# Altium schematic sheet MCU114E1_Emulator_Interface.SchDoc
size 431 x 279 mm; Date: Not shown in title block; ApprovedBy: Not shown in title block; CheckedBy: Not shown in title block; Author: Not shown in title block; CompanyName: Not shown in title block; Engineer: Not shown in title block; Organization: Not shown in title block; Address1: Not shown in title block; Address2: Not shown in title block; Address3: Not shown in title block; Address4: Not shown in title block; DocumentNumber: 10; Revision: Use project parameter SCH_Rev; SheetNumber: 10; SheetTotal: 11; PageSetup: Record=PageOptions¦CenterHorizontal=True¦CenterVertical=True¦PrintScale=1.00¦XCorrection=1.00¦YCorrection=1.00¦PrintKind=0¦BorderSize=5000000¦LeftOffset=0¦BottomOffset=0¦Orientation=2¦PaperLength=1000¦PaperWidth=1000¦Scale=100¦PaperSource=15¦PrintQuality=600¦MediaType=1¦DitherType=10¦PaperKind=Letter¦PrintScaleMode=1
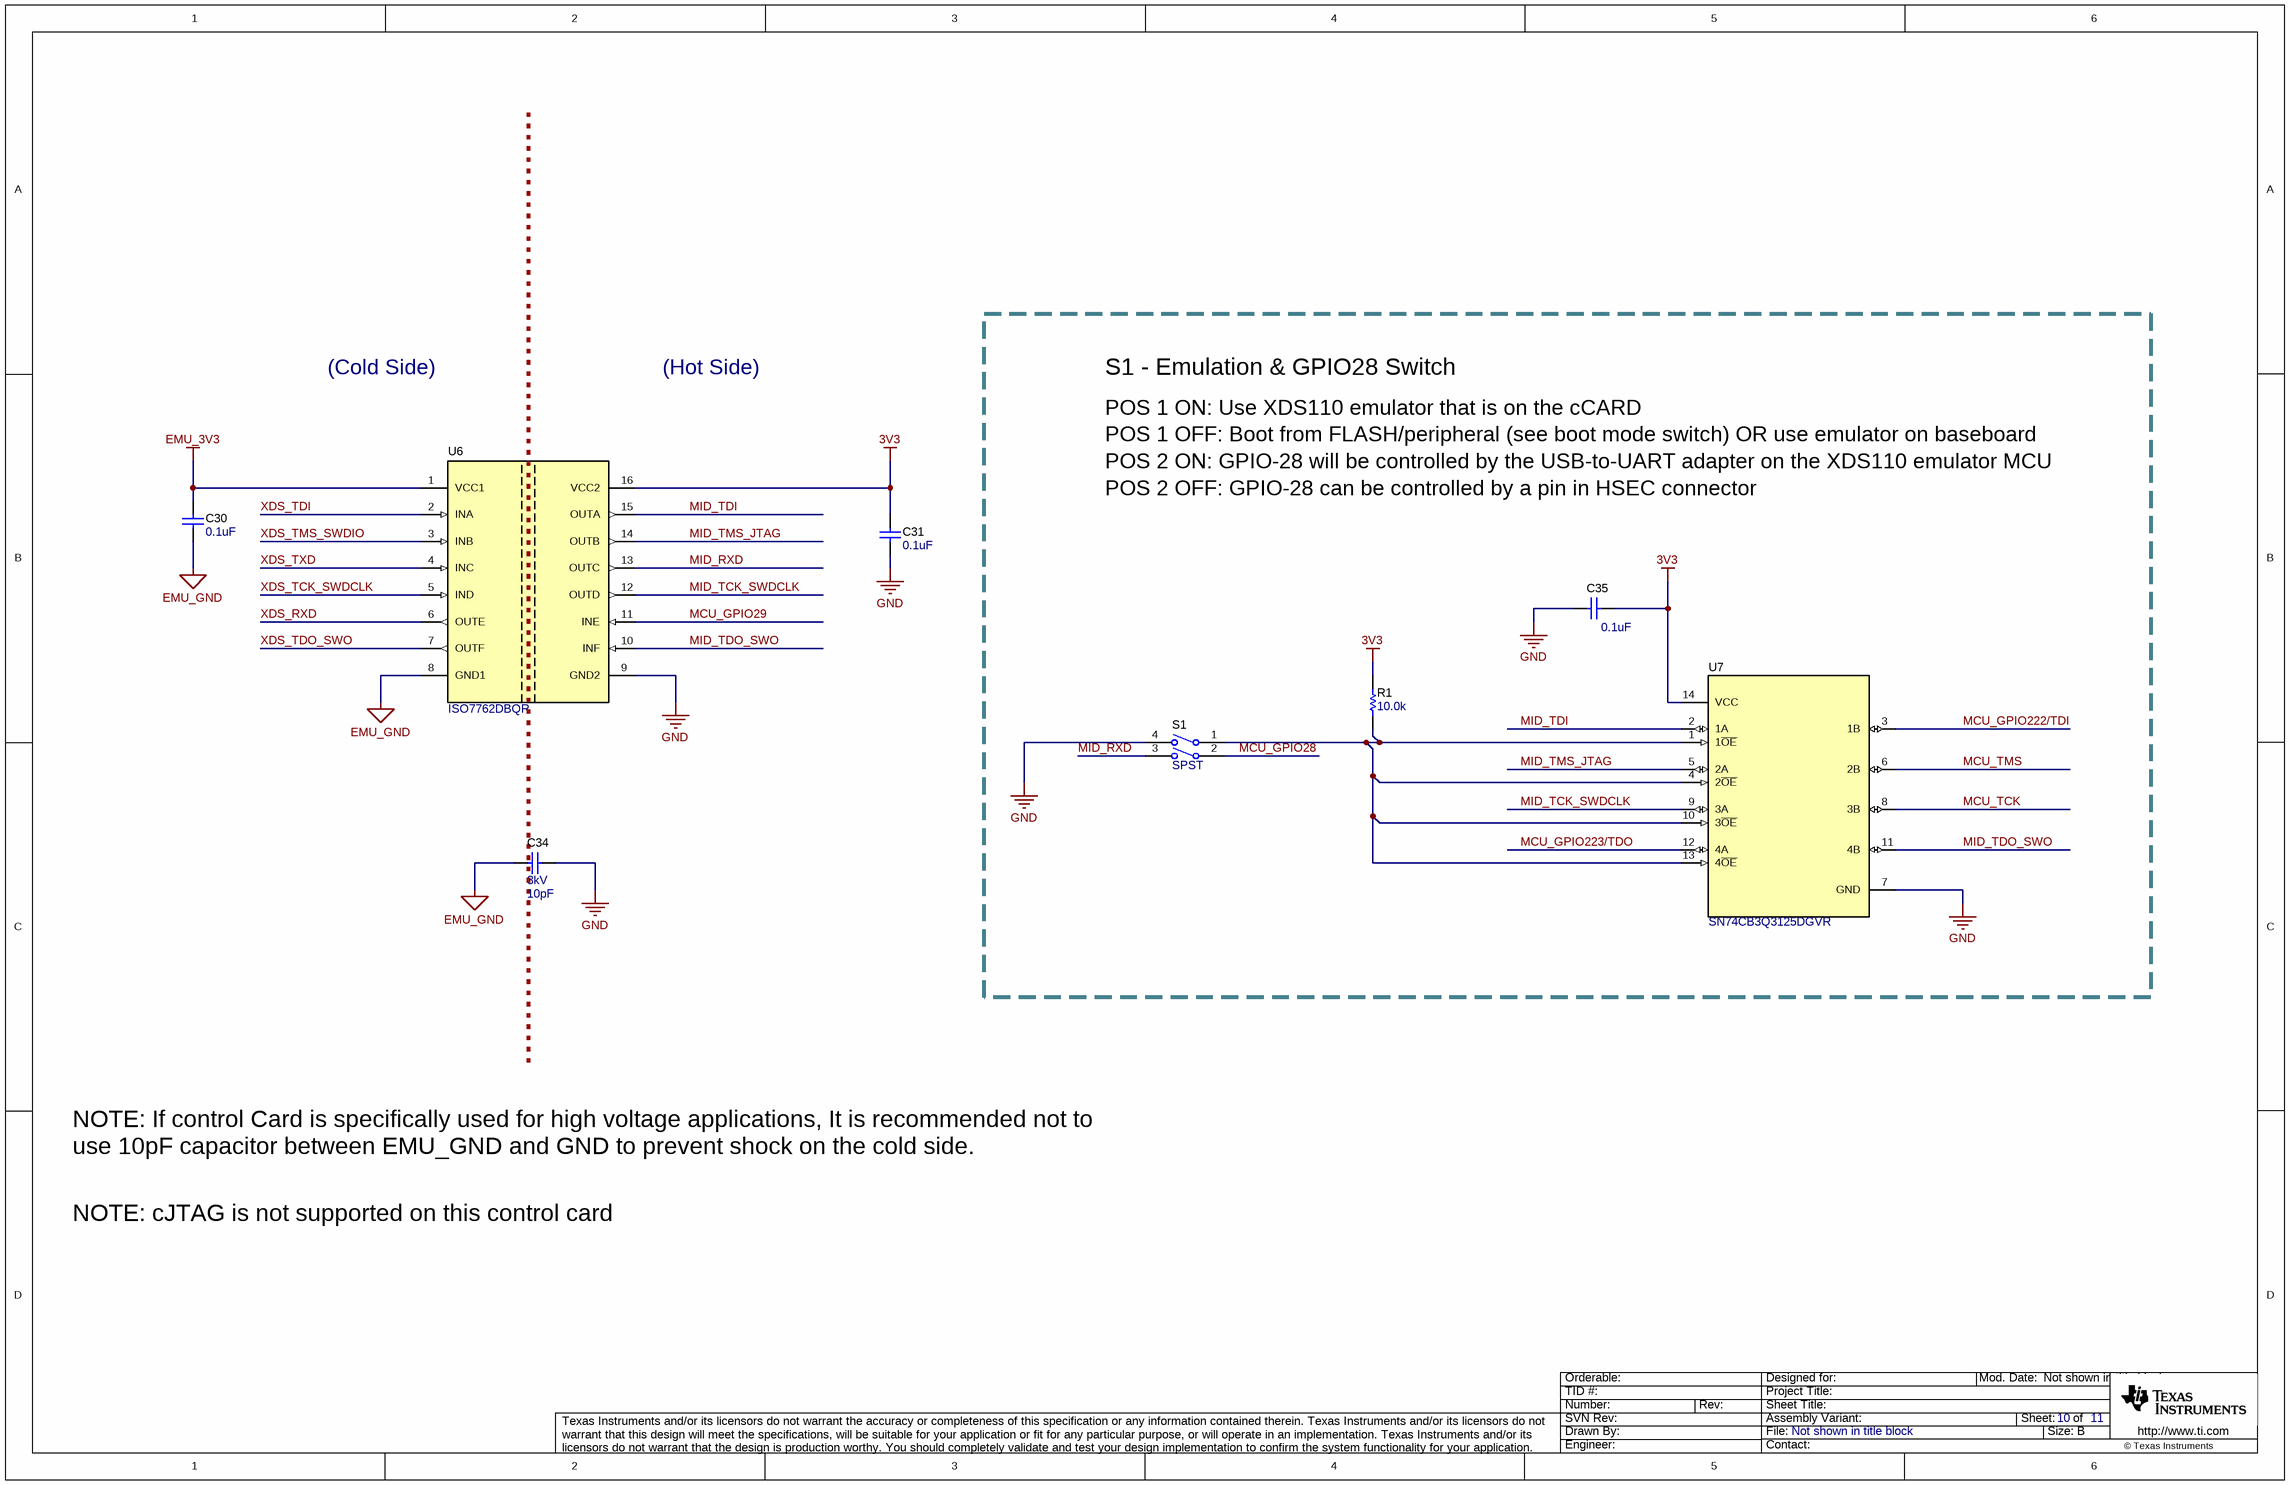
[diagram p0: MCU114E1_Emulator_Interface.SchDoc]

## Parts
C30  ValueDisplayed: 0.1uF  [0402]  (hidden comment: 885012205037)
C31  ValueDisplayed: 0.1uF  [0402]  (hidden comment: 885012205037)
C34  VDC_V: 3kV  ValueDisplayed: 10pF  [1812_180]  (hidden comment: C1812C100JHGACTU)
C35  ValueDisplayed: 0.1uF  [0402]  (hidden comment: 885012205037)
R1  ValueDisplayed: 10.0k  [0402]  (hidden comment: AC0402FR-0710KL)
S1  Circuit: SPST  [SW_218-2LP]  (hidden comment: 218-2LPST)
U6  ISO7762DBQR  [DBQ0016A_N]
U7  SN74CB3Q3125DGVR  [DGV0014A_N]

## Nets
3V3: C31.1 C35.1 R1.2 U6.16(VCC2) U7.14(VCC)
EMU_3V3: C30.1 U6.1(VCC1)
EMU_GND: C30.2 C34.2 U6.8(GND1)
GND: C31.2 C34.1 C35.2 S1.4 U6.9(GND2) U7.7(GND)
MCU_GPIO28: S1.2
MCU_GPIO29: U6.11(INE)
MCU_GPIO222/TDI: U7.3(1B)
MCU_GPIO223/TDO: U7.12(4A)
MCU_TCK: U7.8(3B)
MCU_TMS: U7.6(2B)
MID_RXD: S1.3 U6.13(OUTC)
MID_TCK_SWDCLK: U6.12(OUTD) U7.9(3A)
MID_TDI: U6.15(OUTA) U7.2(1A)
MID_TDO_SWO: U6.10(INF) U7.11(4B)
MID_TMS_JTAG: U6.14(OUTB) U7.5(2A)
XDS_RXD: U6.6(OUTE)
XDS_TCK_SWDCLK: U6.5(IND)
XDS_TDI: U6.2(INA)
XDS_TDO_SWO: U6.7(OUTF)
XDS_TMS_SWDIO: U6.3(INB)
XDS_TXD: U6.4(INC)
NetR1_1: R1.1 S1.1 U7.1(1~{OE}) U7.4(2~{OE}) U7.10(3~{OE}) U7.13(4~{OE})

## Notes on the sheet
- S1 - Emulation & GPIO28 Switch
- (Cold Side)
- (Hot Side)
- POS 1 ON: Use XDS110 emulator that is on the cCARD
- POS 1 OFF: Boot from FLASH/peripheral (see boot mode switch) OR use emulator on baseboard
- POS 2 ON: GPIO-28 will be controlled by the USB-to-UART adapter on the XDS110 emulator MCU
- POS 2 OFF: GPIO-28 can be controlled by a pin in HSEC connector
- NOTE: If control Card is specifically used for high voltage applications, It is recommended not to use 10pF capacitor between EMU_GND and GND to prevent shock on the cold side.
- NOTE: cJTAG is not supported on this control card

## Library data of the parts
C30 C31 C35 = CMP-0006228-2: CAP, CERM, 0.1 uF, 16 V, +/- 10%, X7R, 0402; Manufacturer: Wurth Elektronik; TaMin_C: -55°C; Polarized: N; SizeAreaWB_mm2: 3; Value1: Unknown; U/M: EA; Value: 0.1uF; TaMax_C: 125°C; SizeZ_mm: 0.6; SizeX_mm: 1; SizeY_mm: 0.5; Value2: 16V; Cap_F: 100nF; AEC Category: Q200
C34 = CMP-0082066-1: CAP, CERM, 10 pF, 3000 V,+/- 5%, C0G/NP0, AEC-Q200 Grade 1, 1812; Manufacturer: Kemet; SizeAreaWB_mm2: 23.1; SizeArea_mm2: 14.4; AEC Qualified: Y; AEC Category: Q200; Value: 10pF; TaMax_C: 125°C; SizeZ_mm: 1.8; AEC Grade: 1; Polarized: N; TaMin_C: -55°C; SizeY_mm: 3.2; Value2: 3000V; U/M: EA; SizeX_mm: 4.5; Cap_Case: 1812
R1 = CMP-0077731-1: RES, 10.0 k, 1%, 0.063 W, AEC-Q200 Grade 0, 0402; Manufacturer: Yageo America; Power_W: 63mW; TempCo: 100 ppm/C; Value_Code: 10k0; U/M: EA; Value: 10.0k; EIA_Code: E96; Res_ohm: 10k; SizeX_mm: 1.0; SizeY_mm: 0.5; SizeZ_mm: 0.6; Value2: 0.063W; AEC Qualified: Y; VDC_V: 50V; AEC Grade: 0; AEC Category: Q200
S1 = CMP-0002230-1: Switch, SPST, 2 Pos, 25mA, 24VDC, SMD; Manufacturer: CTS Electrocomponents; VDC_V: 24V; SwitchFunction: Off-On; PositionCount: 2; CurrentRating_mA: 25A
U6 = CMP-0067607-3: High Speed, Robust EMC, Reinforced Six-Channel Digital Isolator, DBQ0016A (SSOP-16); Manufacturer: Texas Instruments; SizeX_mm: 6.0; SizeY_mm: 10.0; CompType: IC; SizeZ_mm: 1.75; SizeArea_mm2: 60.0; SizeAreaWB_mm2: 96.0; U/M: EA; AEC Category: Q200; AEC Qualified: N
U7 = CMP-0066249-2: Quadruple FET 2.5-V/3.3-V Low-Voltage High-Bandwidth Bus Switch, DGV0014A (TVSOP-14); Alternate Manufacturer: Texas Instruments; SizeArea_mm2: 23.04; SizeX_mm: 6.4; SizeAreaWB_mm2: 47.04; CompType: IC; SizeZ_mm: 1.2; AEC Category: Q200; Rating: Catalog; SizeY_mm: 3.6; AEC Qualified: N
